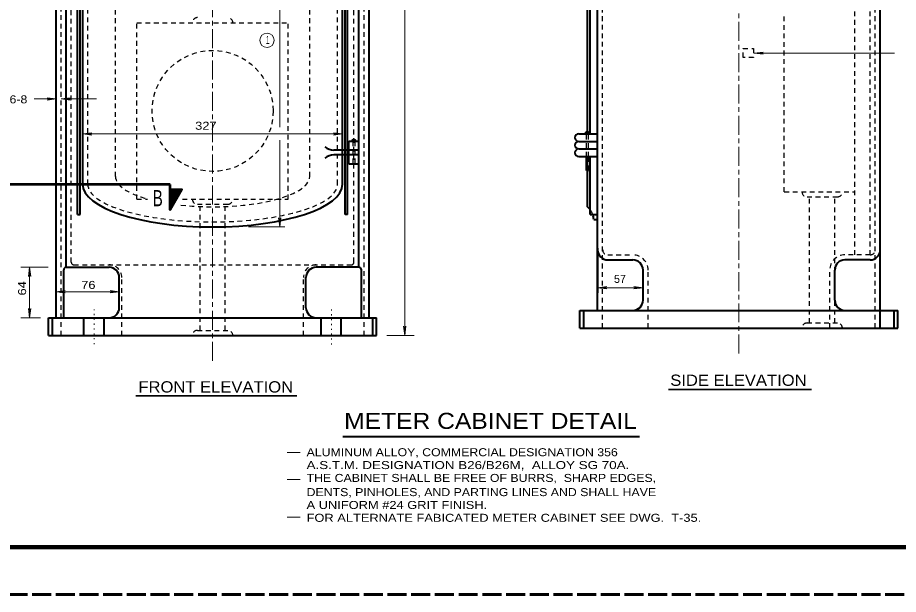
# Model space of a CAD drawing. Extents: x 312583 to 312853, y 144419 to 144586.
# Drawn here: x 312634.8 to 312718.5, y 144418.6 to 144473.4 of the extents above; entities that cross this region are included whole.
import ezdxf
from ezdxf.enums import TextEntityAlignment as Align

# ---------------------------------------------------------------- set-up
doc = ezdxf.new("R2010")
doc.units = 0
doc.header["$LTSCALE"] = 0.3
for name, pattern in [('DOTTED', [1.5, 0.3, -1.2]), ('LONG_DASH_SHORT_DASH', [9.9, 6, -1.2, 1.5, -1.2]), ('LONG_DASHED', [7.5, 6, -1.5]), ('SHORT_DASHED', [2.7, 1.5, -1.2])]:
    doc.linetypes.add(name, pattern=pattern)
doc.layers.add('1', color=7, linetype='Continuous', lineweight=13)

msp = doc.modelspace()

# ---------------------------------------------------------------- linework, layer by layer
at = {"layer": '1', "linetype": 'LONG_DASH_SHORT_DASH'}
for p, q in [((312703.3115, 144441.4612), (312703.3115, 144527.0365)), ((312653.3356, 144440.7591), (312653.3356, 144526.3344))]:
    msp.add_line(p, q, dxfattribs=at)
at = {"layer": '1', "linetype": 'SHORT_DASHED', "lineweight": 25}
for p, q in [((312690.3702, 144443.8839), (312690.3702, 144520.3589)), ((312638.9606, 144443.1818), (312638.9606, 144519.6108)), ((312639.9189, 144450.1278), (312639.9189, 144519.6414)), ((312666.7523, 144450.1278), (312666.7523, 144519.6414)), ((312667.7106, 144443.1818), (312667.7106, 144519.6108)), ((312641.4753, 144457.5568), (312641.4753, 144512.1818)), ((312665.1959, 144457.5568), (312665.1959, 144512.1818)), ((312644.1126, 144458.2774), (312644.1126, 144511.4611)), ((312662.5586, 144458.2774), (312662.5586, 144511.4611)), ((312714.3285, 144450.8299), (312714.3285, 144485.2992)), ((312715.7699, 144450.8299), (312715.7699, 144484.0649)), ((312716.2452, 144443.8839), (312716.2452, 144483.6509)), ((312707.6202, 144456.8252), (312707.6202, 144473.5922)), ((312646.1443, 144472.8901), (312660.5193, 144472.8901)), ((312646.1443, 144456.1231), (312646.1443, 144472.8901)), ((312660.5193, 144456.1231), (312660.5193, 144472.8901)), ((312666.6603, 144461.6201), (312666.6603, 144459.4734)), ((312666.8443, 144461.6201), (312666.8443, 144459.4734)), ((312688.8292, 144460.1755), (312688.8292, 144462.3299)), ((312689.0132, 144460.1755), (312689.0132, 144462.3299)), ((312689.0132, 144458.8645), (312689.0132, 144460.1755)), ((312707.6202, 144456.8252), (312714.3285, 144456.8252)), ((312646.1443, 144456.1231), (312647.1486, 144456.1231)), ((312650.4836, 144456.1231), (312660.5193, 144456.1231)), ((312709.7822, 144456.3422), (312712.6572, 144456.3422)), ((312710.0199, 144444.3669), (312710.0199, 144456.3422)), ((312712.4119, 144444.3669), (312712.4119, 144456.3422)), ((312651.8943, 144455.6401), (312654.7693, 144455.6401)), ((312652.1396, 144443.6648), (312652.1396, 144455.6401)), ((312654.5316, 144443.6648), (312654.5316, 144455.6401)), ((312690.8532, 144450.8299), (312693.2452, 144450.8299)), ((312715.7699, 144450.8299), (312713.3702, 144450.8299)), ((312640.1566, 144449.8901), (312666.5146, 144449.8901)), ((312694.6865, 144443.8839), (312694.6865, 144449.3962)), ((312711.9365, 144443.8839), (312711.9365, 144449.3962)), ((312644.7106, 144443.1818), (312644.7106, 144448.6941)), ((312661.9606, 144443.1818), (312661.9606, 144448.6941)), ((312709.7822, 144444.3669), (312712.6572, 144444.3669)), ((312651.8943, 144443.6648), (312654.7693, 144443.6648))]:
    msp.add_line(p, q, dxfattribs=at)
at = {"layer": '1', "lineweight": 40}
for p, q in [((312716.7282, 144443.8839), (312716.7282, 144520.5735)), ((312638.4776, 144444.8608), (312638.4776, 144519.8484)), ((312639.4359, 144449.6524), (312639.4359, 144519.6261)), ((312667.2276, 144449.6524), (312667.2276, 144519.6261)), ((312668.1859, 144444.8608), (312668.1859, 144519.8484)), ((312640.5169, 144454.6818), (312640.5169, 144512.1818)), ((312640.7546, 144454.6818), (312640.7546, 144512.1818)), ((312665.6713, 144457.5568), (312665.6713, 144512.1818)), ((312665.9089, 144454.6818), (312665.9089, 144512.1818)), ((312666.1543, 144454.6818), (312666.1543, 144512.1818)), ((312688.9365, 144462.3299), (312688.9365, 144508.8129)), ((312689.1742, 144462.3299), (312689.1742, 144508.8129)), ((312640.9999, 144457.5568), (312640.9999, 144482.2358)), ((312666.2693, 144461.6278), (312667.2276, 144461.6278)), ((312666.2693, 144459.4734), (312666.2693, 144461.6278)), ((312688.0932, 144462.3299), (312689.8949, 144462.3299)), ((312688.0932, 144461.6169), (312689.8949, 144461.6169)), ((312667.2046, 144460.7691), (312664.8586, 144460.7691)), ((312688.0932, 144460.8962), (312689.8949, 144460.8962)), ((312667.2046, 144460.3321), (312664.8586, 144460.3321)), ((312688.0932, 144460.1755), (312689.8949, 144460.1755)), ((312688.8292, 144458.8645), (312688.8292, 144460.1755)), ((312688.9365, 144455.3839), (312688.9365, 144460.1755)), ((312689.1742, 144454.6632), (312689.1742, 144460.1755)), ((312666.2693, 144459.4734), (312667.2276, 144459.4734)), ((312688.8292, 144458.8645), (312689.0132, 144458.8645)), ((312640.5169, 144454.6818), (312640.7546, 144454.6818)), ((312666.1543, 144454.6818), (312665.9089, 144454.6818)), ((312689.1742, 144454.6632), (312689.8949, 144454.6632)), ((312689.5192, 144454.1879), (312689.8949, 144454.1879)), ((312690.8532, 144450.3545), (312693.2452, 144450.3545)), ((312715.7699, 144450.3545), (312713.3702, 144450.3545)), ((312639.1983, 144444.8608), (312639.1983, 144449.4148)), ((312639.4359, 144449.6524), (312643.5146, 144449.6524)), ((312667.2276, 144449.6524), (312663.1566, 144449.6524)), ((312667.4729, 144444.8608), (312667.4729, 144449.4148)), ((312694.2035, 144446.5212), (312694.2035, 144449.3962)), ((312712.4119, 144446.5212), (312712.4119, 144449.3962)), ((312644.4729, 144445.8191), (312644.4729, 144448.6941)), ((312662.1983, 144445.8191), (312662.1983, 144448.6941)), ((312688.2159, 144445.5629), (312718.4072, 144445.5629)), ((312688.2159, 144443.8839), (312688.2159, 144445.5629)), ((312688.5762, 144443.8839), (312688.5762, 144445.5629)), ((312718.0469, 144443.8839), (312718.0469, 144445.5629)), ((312718.4072, 144443.8839), (312718.4072, 144445.5629)), ((312637.7646, 144444.8608), (312668.9066, 144444.8608)), ((312637.7646, 144443.1818), (312637.7646, 144444.8608)), ((312638.1249, 144443.1818), (312638.1249, 144444.8608)), ((312641.1149, 144443.1818), (312641.1149, 144444.8608)), ((312643.0316, 144443.1818), (312643.0316, 144444.8608)), ((312663.6396, 144443.1818), (312663.6396, 144444.8608)), ((312665.5563, 144443.1818), (312665.5563, 144444.8608)), ((312668.5463, 144443.1818), (312668.5463, 144444.8608)), ((312668.9066, 144443.1818), (312668.9066, 144444.8608)), ((312688.2159, 144443.8839), (312718.4072, 144443.8839)), ((312637.7646, 144443.1818), (312668.9066, 144443.1818)), ((312665.6992, 144433.5949), (312693.865, 144433.5949))]:
    msp.add_line(p, q, dxfattribs=at)
at = {"layer": '1'}
for p, q in [((312671.5823, 144443.1818), (312671.5823, 144519.8484)), ((312659.7066, 144462.9541), (312659.7066, 144516.2528)), ((312704.7452, 144469.9965), (312705.6115, 144470.1039)), ((312704.7452, 144469.9965), (312718.0775, 144469.9965)), ((312704.7452, 144469.9965), (312705.6115, 144469.8892)), ((312705.6115, 144470.1039), (312705.3355, 144469.9965)), ((312705.6115, 144469.8892), (312705.3355, 144469.9965)), ((312636.3769, 144465.6451), (312638.4776, 144465.6451)), ((312637.6113, 144465.7524), (312637.8873, 144465.6451)), ((312638.4776, 144465.6451), (312637.6113, 144465.7524)), ((312637.6113, 144465.5378), (312637.8873, 144465.6451)), ((312638.4776, 144465.6451), (312637.6113, 144465.5378)), ((312638.9606, 144465.6451), (312639.8269, 144465.7524)), ((312638.9606, 144465.6451), (312642.3186, 144465.6451)), ((312638.9606, 144465.6451), (312639.8269, 144465.5378)), ((312639.8269, 144465.7524), (312639.5509, 144465.6451)), ((312639.8269, 144465.5378), (312639.5509, 144465.6451)), ((312640.9999, 144462.3178), (312641.8663, 144462.4251)), ((312640.9999, 144462.3178), (312665.6713, 144462.3178)), ((312640.9999, 144462.3178), (312641.8663, 144462.2104)), ((312641.8663, 144462.4251), (312641.5903, 144462.3178)), ((312641.8663, 144462.2104), (312641.5903, 144462.3178)), ((312659.7066, 144453.4858), (312659.7066, 144461.7428)), ((312664.8049, 144462.4251), (312665.0809, 144462.3178)), ((312665.6713, 144462.3178), (312664.8049, 144462.4251)), ((312664.8049, 144462.2104), (312665.0809, 144462.3178)), ((312665.6713, 144462.3178), (312664.8049, 144462.2104)), ((312659.5993, 144454.3521), (312659.7066, 144454.0761)), ((312659.7066, 144453.4858), (312659.5993, 144454.3521)), ((312659.8139, 144454.3521), (312659.7066, 144454.0761)), ((312659.7066, 144453.4858), (312659.8139, 144454.3521)), ((312656.7549, 144453.4858), (312660.2049, 144453.4858)), ((312689.9332, 144447.2419), (312689.9332, 144451.4662)), ((312637.7263, 144449.6524), (312635.1273, 144449.6524)), ((312635.9553, 144449.6524), (312635.8479, 144448.7861)), ((312635.8479, 144448.7861), (312635.9553, 144449.0621)), ((312635.9553, 144444.8608), (312635.9553, 144449.6524)), ((312635.9553, 144449.6524), (312636.0626, 144448.7861)), ((312636.0626, 144448.7861), (312635.9553, 144449.0621)), ((312638.4776, 144447.3371), (312639.3439, 144447.4444)), ((312639.3439, 144447.4444), (312639.0679, 144447.3371)), ((312643.6066, 144447.4444), (312643.8826, 144447.3371)), ((312644.4729, 144447.3371), (312643.6066, 144447.4444)), ((312689.8949, 144447.7095), (312690.7612, 144447.8169)), ((312689.8949, 144447.7095), (312694.2035, 144447.7095)), ((312689.8949, 144447.7095), (312690.7612, 144447.6022)), ((312690.7612, 144447.8169), (312690.4852, 144447.7095)), ((312690.7612, 144447.6022), (312690.4852, 144447.7095)), ((312693.3372, 144447.8169), (312693.6132, 144447.7095)), ((312694.2035, 144447.7095), (312693.3372, 144447.8169)), ((312693.3372, 144447.6022), (312693.6132, 144447.7095)), ((312694.2035, 144447.7095), (312693.3372, 144447.6022)), ((312638.4776, 144447.3371), (312644.4729, 144447.3371)), ((312638.4776, 144447.3371), (312639.3439, 144447.2298)), ((312639.3439, 144447.2298), (312639.0679, 144447.3371)), ((312643.6066, 144447.2298), (312643.8826, 144447.3371)), ((312644.4729, 144447.3371), (312643.6066, 144447.2298)), ((312635.8479, 144445.7271), (312635.9553, 144445.4511)), ((312635.9553, 144444.8608), (312635.8479, 144445.7271)), ((312636.0626, 144445.7271), (312635.9553, 144445.4511)), ((312635.9553, 144444.8608), (312636.0626, 144445.7271)), ((312636.9979, 144444.8608), (312635.1273, 144444.8608)), ((312671.475, 144444.0481), (312671.5823, 144443.7721)), ((312671.5823, 144443.1818), (312671.475, 144444.0481)), ((312671.6897, 144444.0481), (312671.5823, 144443.7721)), ((312671.5823, 144443.1818), (312671.6897, 144444.0481)), ((312669.8649, 144443.1818), (312672.4653, 144443.1818)), ((312660.4116, 144432.0692), (312661.6612, 144432.0692)), ((312660.4116, 144429.5068), (312661.6612, 144429.5068)), ((312660.4116, 144425.9284), (312661.6612, 144425.9284))]:
    msp.add_line(p, q, dxfattribs=at)
at = {"layer": '1', "lineweight": 53}
for p, q in [((312649.2953, 144457.5108), (312632.7046, 144457.5108)), ((312649.2953, 144457.0354), (312649.2953, 144457.5108))]:
    msp.add_line(p, q, dxfattribs=at)
at = {"layer": '1', "lineweight": 35}
for p, q in [((312649.2953, 144457.0201), (312650.1156, 144456.5448)), ((312649.2953, 144456.9894), (312650.1079, 144456.5218)), ((312649.2953, 144456.9588), (312650.0926, 144456.4988)), ((312649.2953, 144456.9358), (312650.0849, 144456.4834)), ((312649.2953, 144456.9051), (312650.0696, 144456.4604)), ((312649.2953, 144456.8284), (312650.0389, 144456.3991)), ((312649.2953, 144456.7978), (312650.0236, 144456.3761)), ((312649.2953, 144456.7671), (312650.0083, 144456.3608)), ((312649.2953, 144456.7441), (312650.0006, 144456.3378)), ((312649.2953, 144456.7134), (312649.9853, 144456.3148)), ((312649.2953, 144456.6828), (312649.9699, 144456.2918)), ((312649.2953, 144456.6598), (312649.9623, 144456.2764)), ((312649.2953, 144456.5984), (312649.9393, 144456.2304)), ((312649.3029, 144456.8821), (312650.0619, 144456.4374)), ((312649.3029, 144456.8514), (312650.0466, 144456.4221)), ((312649.3029, 144456.6291), (312649.9469, 144456.2534)), ((312649.3183, 144457.0354), (312650.1309, 144456.5601)), ((312649.3719, 144457.0354), (312650.1386, 144456.5908)), ((312649.4103, 144457.0354), (312650.1539, 144456.6061)), ((312649.4639, 144457.0354), (312650.1616, 144456.6291)), ((312649.5099, 144457.0354), (312650.1769, 144456.6521)), ((312649.5559, 144457.0354), (312650.1923, 144456.6674)), ((312649.6019, 144457.0354), (312650.1999, 144456.6904)), ((312649.6556, 144457.0354), (312650.2153, 144456.7134)), ((312649.7016, 144457.0354), (312650.2306, 144456.7288)), ((312649.7476, 144457.0354), (312650.2383, 144456.7518)), ((312649.8013, 144457.0354), (312650.2536, 144456.7671)), ((312649.8473, 144457.0354), (312650.2613, 144456.7901)), ((312649.8933, 144457.0354), (312650.2766, 144456.8131)), ((312649.9469, 144457.0354), (312650.2843, 144456.8284)), ((312649.9929, 144457.0354), (312650.2996, 144456.8591)), ((312650.0389, 144457.0354), (312650.3073, 144456.8744)), ((312650.0849, 144457.0354), (312650.3226, 144456.8974)), ((312650.1386, 144457.0354), (312650.3303, 144456.9204)), ((312650.1769, 144457.0354), (312650.3456, 144456.9358)), ((312650.2306, 144457.0354), (312650.3533, 144456.9588)), ((312650.2766, 144457.0354), (312650.3686, 144456.9818)), ((312650.3303, 144457.0354), (312650.3839, 144456.9971)), ((312650.3763, 144457.0354), (312650.3916, 144457.0201)), ((312649.2953, 144456.5754), (312649.9239, 144456.2151)), ((312649.2953, 144456.5524), (312649.9163, 144456.1921)), ((312649.2953, 144456.5218), (312649.9009, 144456.1691)), ((312649.2953, 144456.4911), (312649.8933, 144456.1538)), ((312649.2953, 144456.4604), (312649.8779, 144456.1308)), ((312649.2953, 144456.4374), (312649.8703, 144456.1078)), ((312649.2953, 144456.4068), (312649.8549, 144456.0924)), ((312649.2953, 144456.3531), (312649.8319, 144456.0464)), ((312649.2953, 144456.3301), (312649.8166, 144456.0234)), ((312649.2953, 144456.2994), (312649.8089, 144456.0004)), ((312649.2953, 144456.2688), (312649.7936, 144455.9851)), ((312649.2953, 144456.2458), (312649.7859, 144455.9621)), ((312649.2953, 144456.2151), (312649.7706, 144455.9391)), ((312649.2953, 144456.1844), (312649.7629, 144455.9238)), ((312649.2953, 144456.1614), (312649.7476, 144455.9008)), ((312649.2953, 144456.1308), (312649.7399, 144455.8778)), ((312649.2953, 144456.1001), (312649.7246, 144455.8624)), ((312649.2953, 144456.0771), (312649.7169, 144455.8394)), ((312649.2953, 144456.0541), (312649.7016, 144455.8164)), ((312649.2953, 144456.0234), (312649.6939, 144455.7934)), ((312649.2953, 144455.9928), (312649.6786, 144455.7781)), ((312649.2953, 144455.9621), (312649.6633, 144455.7551)), ((312649.2953, 144455.9391), (312649.6556, 144455.7321)), ((312649.2953, 144455.9084), (312649.6403, 144455.7168)), ((312649.2953, 144455.8854), (312649.6249, 144455.6938)), ((312649.2953, 144455.8548), (312649.6173, 144455.6708)), ((312649.2953, 144455.8318), (312649.6019, 144455.6554)), ((312649.2953, 144455.8011), (312649.5943, 144455.6324)), ((312649.2953, 144455.7704), (312649.5789, 144455.6094)), ((312649.2953, 144455.7474), (312649.5713, 144455.5941)), ((312649.3029, 144456.3838), (312649.8473, 144456.0618)), ((312649.2953, 144455.7168), (312649.5559, 144455.5634)), ((312649.2953, 144455.6938), (312649.5483, 144455.5481)), ((312649.2953, 144455.6631), (312649.5329, 144455.5251)), ((312649.2953, 144455.6324), (312649.5253, 144455.5021)), ((312649.2953, 144455.6094), (312649.5099, 144455.4868)), ((312649.2953, 144455.5788), (312649.5023, 144455.4638)), ((312649.2953, 144455.5558), (312649.4869, 144455.4408)), ((312649.2953, 144455.5251), (312649.4716, 144455.4254)), ((312649.2953, 144455.4944), (312649.4639, 144455.4024)), ((312649.2953, 144455.4638), (312649.4486, 144455.3794)), ((312649.2953, 144455.4408), (312649.4333, 144455.3641)), ((312649.2953, 144455.4101), (312649.4256, 144455.3411)), ((312649.2953, 144455.3871), (312649.4103, 144455.3181)), ((312649.2953, 144455.3641), (312649.4026, 144455.2951)), ((312649.2953, 144455.3334), (312649.3873, 144455.2798)), ((312649.2953, 144455.3028), (312649.3796, 144455.2568)), ((312649.2953, 144455.2721), (312649.3643, 144455.2338)), ((312649.2953, 144455.2491), (312649.3566, 144455.2184)), ((312649.2953, 144455.2184), (312649.3413, 144455.1954)), ((312649.2953, 144455.1954), (312649.3336, 144455.1724)), ((312649.2953, 144455.1648), (312649.3183, 144455.1571)), ((312649.2953, 144455.1341), (312649.3106, 144455.1341)), ((312646.0571, 144437.4394), (312661.3311, 144437.4394)), ((312696.6148, 144438.0474), (312710.2073, 144438.0474))]:
    msp.add_line(p, q, dxfattribs=at)
at = {"layer": '1', "linetype": 'DOTTED'}
for p, q in [((312642.0733, 144442.3614), (312642.0733, 144445.6351)), ((312664.6363, 144442.3308), (312664.6363, 144445.6581))]:
    msp.add_line(p, q, dxfattribs=at)
at = {"layer": '1', "lineweight": 158}
msp.add_line((312616.5, 144423.0846), (312849, 144423.0846), dxfattribs=at)
at = {"layer": '1', "linetype": 'LONG_DASHED', "lineweight": 60}
msp.add_line((312851.75, 144418.5846), (312583.526, 144418.5846), dxfattribs=at)
msp.add_line((312851.75, 144418.5846), (312583.526, 144418.5846), dxfattribs=at)
at = {"layer": '1', "lineweight": 40}
msp.add_lwpolyline([(312689.8949, 144445.5629), (312689.8949, 144520.5735), (312703.3115, 144520.8112)], dxfattribs=at)
at = {"layer": '1', "linetype": 'SHORT_DASHED', "lineweight": 25}
msp.add_lwpolyline([(312703.7102, 144469.5979), (312703.7102, 144470.4335), (312704.7069, 144470.4335), (312704.7069, 144469.5979)], close=True, dxfattribs=at)
at = {"layer": '1', "lineweight": 53}
msp.add_lwpolyline([(312649.2953, 144457.0354), (312650.4069, 144457.0354), (312649.2953, 144455.1188)], close=True, dxfattribs=at)
at = {"layer": '1'}
msp.add_circle((312658.501, 144471.2149), 0.6818, dxfattribs=at)
at = {"layer": '1', "linetype": 'SHORT_DASHED', "lineweight": 25}
msp.add_circle((312653.3337, 144464.5066), 5.75, dxfattribs=at)
for centre, radius, start, end in [((312651.8962, 144472.892), 0.4792, 90, 180), ((312654.7712, 144472.892), 0.4792, 0, 90), ((312709.7784, 144456.8233), 0.4792, 180, 270), ((312712.6534, 144456.8233), 0.4792, 270, 0), ((312651.8962, 144456.1212), 0.4792, 180, 270), ((312654.7712, 144456.1212), 0.4792, 270, 0), ((312687.8295, 144454.104), 1.6924, 19.43327, 37.3863), ((312690.8513, 144451.3129), 0.4792, 180, 270), ((312693.2471, 144449.3962), 1.4375, 0, 90), ((312713.3721, 144449.3962), 1.4375, 90, 180), ((312715.768, 144451.3129), 0.4792, 270, 0), ((312640.1566, 144450.1316), 0.2396, 180, 270), ((312643.5108, 144448.6941), 1.1979, 0, 90), ((312663.1566, 144448.6941), 1.1979, 90, 180), ((312666.5108, 144450.1316), 0.2396, 270, 0), ((312709.7784, 144443.8858), 0.4792, 90, 180), ((312712.6534, 144443.8858), 0.4792, 0, 90), ((312651.8962, 144443.1837), 0.4792, 90, 180), ((312654.7712, 144443.1837), 0.4792, 0, 90)]:
    msp.add_arc(centre, radius, start, end, dxfattribs=at)
at = {"layer": '1', "lineweight": 40}
for centre, radius, start, end in [((312688.9135, 144462.2495), 0.2436, 20.21131, 159.74458), ((312688.9188, 144462.2706), 0.1827, 20.21131, 159.74458), ((312666.7517, 144461.5867), 0.1954, 17.35766, 165.56497), ((312666.7499, 144461.5984), 0.1465, 17.35766, 165.56497), ((312666.7501, 144461.6101), 0.0977, 17.35766, 165.56497), ((312666.746, 144461.6277), 0.0244, 17.35766, 165.56497), ((312688.0961, 144461.9743), 0.3594, 90.15279, 269.84721), ((312688.0961, 144461.2556), 0.3594, 90.15279, 269.84721), ((312688.9228, 144462.2864), 0.137, 20.21131, 159.74458), ((312688.9257, 144462.2982), 0.1028, 20.21131, 159.74458), ((312664.9241, 144462.2929), 1.5233, 231.73709, 267.53516), ((312688.0961, 144460.5368), 0.3594, 90.15279, 269.84721), ((312664.9241, 144458.814), 1.5233, 92.46484, 128.26291), ((312687.8295, 144454.104), 1.6924, 37.36588, 49.23213), ((312687.8295, 144454.104), 1.6924, 3.22959, 19.4309), ((312690.8513, 144451.3129), 0.9583, 180, 270), ((312715.768, 144451.3129), 0.9583, 270, 0), ((312693.2471, 144449.3962), 0.9583, 0, 90), ((312713.3721, 144449.3962), 0.9583, 90, 180), ((312639.4378, 144449.4129), 0.2396, 90, 180), ((312643.5108, 144448.6941), 0.9583, 0, 90), ((312663.1566, 144448.6941), 0.9583, 90, 180), ((312667.2295, 144449.4129), 0.2396, 0, 90), ((312643.5108, 144445.8191), 0.9583, 270, 0), ((312663.1566, 144445.8191), 0.9583, 180, 270), ((312693.2471, 144446.5212), 0.9583, 270, 0), ((312713.3721, 144446.5212), 0.9583, 180, 270)]:
    msp.add_arc(centre, radius, start, end, dxfattribs=at)
at = {"layer": '1', "linetype": 'SHORT_DASHED', "lineweight": 25}
for centre, major_axis, ratio, start_param, end_param in [((312653.3346, 144458.2774), (-9.224, 0), 0.311688, 6.2831853, 7.1291245), ((312653.3346, 144458.2774), (-9.224, 0), 0.311688, 1.2393571, 3.1415927), ((312653.3346, 144457.5587), (11.8594, 0), 0.30303, 3.1415927, 6.2831853)]:
    msp.add_ellipse(centre, major_axis=major_axis, ratio=ratio, start_param=start_param, end_param=end_param, dxfattribs=at)
at = {"layer": '1', "lineweight": 40}
msp.add_ellipse((312653.3346, 144457.5587), major_axis=(12.3385, 0), ratio=0.330097, start_param=3.1415927, end_param=6.2831853, dxfattribs=at)

# ---------------------------------------------------------------- texts
at = {"layer": '1'}
for s, width, p in [('1', 0.5, (312658.3928, 144470.8721)), ('6-8', 1.15, (312634.0518, 144465.225)), ('327 ', 1.2, (312651.6805, 144462.7194)), ('76 ', 1.2, (312640.8577, 144447.5985)), ('ALUMINUM ALLOY, COMMERCIAL DESIGNATION 356', 1.15, (312662.2592, 144431.7079)), ('A.S.T.M. DESIGNATION B26/B26M,  ALLOY SG 70A.', 1.25, (312662.2592, 144430.4879)), ('THE CABINET SHALL BE FREE OF BURRS,  SHARP EDGES,', 1.15, (312662.2592, 144429.2679)), ('DENTS, PINHOLES, AND PARTING LINES AND SHALL HAVE', 1.15, (312662.2592, 144427.9187)), ('A UNIFORM #24 GRIT FINISH.', 1.2, (312662.2592, 144426.6987)), ('FOR ALTERNATE FABICATED METER CABINET SEE DWG.  T-35.', 1.2, (312662.2592, 144425.4787))]:
    msp.add_text(s, height=0.76, dxfattribs=dict(at, width=width)).set_placement(p)
for s, height, width, p in [('B', 1.533, 0.7, (312648.1261, 144455.4561)), ('SIDE ELEVATION', 1.07, 1.1, (312703.2623, 144438.3931)), ('FRONT ELEVATION', 1.07, 1.1, (312653.6329, 144437.7612)), ('METER CABINET DETAIL', 1.52, 1.15, (312679.7208, 144434.3087))]:
    msp.add_text(s, height=height, dxfattribs=dict(at, width=width)).set_placement(p, align=Align.CENTER)
at = {"layer": '1', "width": 1.2}
msp.add_text('64 ', height=0.76, rotation=90, dxfattribs=at).set_placement((312635.6247, 144446.9779))
at = {"layer": '1'}
msp.add_text('57', height=0.76, dxfattribs=at).set_placement((312691.4493, 144448.1721))

doc.saveas('drawing.dxf')
